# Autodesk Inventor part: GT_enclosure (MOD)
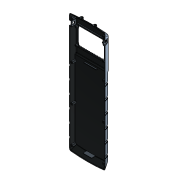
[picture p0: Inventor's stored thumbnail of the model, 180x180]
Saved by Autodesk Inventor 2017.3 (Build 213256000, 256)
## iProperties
Created: 2017-06
Part Number: GT_enclosure (MOD)
Material: ABS Plastic
Document SubType Name: Modeling
Designer: MQ42926084
Density: 1.06 g/cm^3
Appearance: Iron Gray
Mass: 305.571 g
Surface Area: 2134.12 cm^2
Volume: 288.274 cm^3
Author: MQ42926084
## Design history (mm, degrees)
sketch "Sketch1"
  geometry: L1 (-82, 271.181)-(-82, 0); L2 (82, 0)-(82, 271.181); L3 (0, -564)-(0, 416) reference; L4 (-120.006, 0)-(146.034, 0) reference; L5 (108.028, 276)-(-79.835, 276); L6 (82, 0)-(-82, 0); A1 r 700 centre (0, -424) between (82, 271.181) and (-82, 271.181); 1 further point
  constraints: 8 end point, 3 point on line, 2 point on circle, 1 centre point, 1 horizontal, 1 parallel, 1 tangent, 1 other
  dimensions: "d0" = 164 distance between parallel lines of L1 L2; "d4" = 700 radius of A1; "d8" = 276 distance between parallel lines of L4 L5
extrude "Extrusion1" new body sketch "Sketch1" distance "d2" = 25; taper "d3" = 0 deg
mirror "Mirror1"
workplane "Work Plane1"
sketch "Sketch7"
  geometry: L1 (0, -44.7)-(0, 268.2) reference; L2 (-80.78, 0)-(80.78, 0) reference; L3 (57.7, 223.5)-(-57.7, 223.5); L4 (-57.7, 223.5)-(-57.7, 142.5); L5 (-57.7, 142.5)-(57.7, 142.5); L6 (57.7, 142.5)-(57.7, 223.5); L7 (57.7, 183)-(-57.7, 183); 1 further point
  constraints: 10 end point, 2 midpoint, 2 parallel, 1 horizontal, 1 perpendicular, 1 other
  dimensions: "d67" = 81 distance between parallel lines of L5 L3; "d68" = 115.4 distance between parallel lines of L4 L6; "d69" = 183 distance between parallel lines of L7 L2
extrude "Extrusion7" cut sketch "Sketch7" distance "d70" = 108; taper "d71" = 0 deg
workplane "Work Plane2"
workplane "Work Plane4"
sketch "Sketch16"
  geometry: L1 (0, -386.4)-(0, 386.4) reference; L2 (-104.358, 0)-(104.076, 0) reference; L3 (72.3, -249)-(72.3, 251.8); C1 r 1.8 at (72.3, -249); C2 r 1.8 at (72.3, -85); C3 r 1.8 at (72.3, 79); C4 r 1.8 at (72.3, 251.8); 3 further points
  constraints: 4 centre point, 4 point on line, 2 end point, 1 coincident, 1 parallel
  dimensions: "d120" = 27 vertical distance of point (0, -276) L3.start; "d121" = 3.6 diameter of C1; "d125" = 144.6 diameter of L3 L1; "d129" = 3.6 diameter of C2 (derived); "d130" = 3.6 diameter of C3 (derived); "d131" = 3.6 diameter of C4 (derived); "d132" = 24.2 vertical distance of point (0, 276) L3.end; "d133" = 164 distance of C2.centre L3.start; "d134" = 164 distance of C3.centre C2.centre; "d135" = 172.8 distance of L3.end C3.centre (derived); "d311" = 249 distance from line of L2 L3.start
extrude "Extrusion13" cut sketch "Sketch16" distance "d126" = 16.8; taper "d127" = 0 deg
mirror "Mirror10"
chamfer "Chamfer6" distance "d141" = 25; stored, may be unused: second distance "d142" = 25, angle "d143" = 45 deg
chamfer "Chamfer7" distance "d144" = 23.7; stored, may be unused: second distance "d145" = 25, angle "d146" = 45 deg
chamfer "Chamfer8" distance "d147" = 25; stored, may be unused: second distance "d148" = 8, angle "d149" = 20 deg
chamfer "Chamfer9" distance "d150" = 25; stored, may be unused: second distance "d151" = 25, angle "d152" = 20 deg
sketch "Sketch17"
  geometry: L1 (-115, -106)-(115, -106); L2 (115, -106)-(115, 300); L3 (115, 300)-(-115, 300); L4 (-115, 300)-(-115, -106); L5 (0, 415.2)-(0, -391.2) reference; L6 (161, 0)-(-161, 0) reference; 1 further point
  constraints: 8 end point, 2 parallel, 1 horizontal, 1 perpendicular, 1 other
  dimensions: "d155" = 106 distance between parallel lines of L6 L1; "d156" = 230 distance between parallel lines of L2 L4; "d157" = 300 distance between parallel lines of L3 L6
extrude "Extrusion14" cut sketch "Sketch17" distance "d153" = 4; taper "d154" = 0 deg
fillet "Fillet19" dims "d158" = 10
fillet "Fillet20" dims "d159" = 4
fillet "Fillet21" dims "d160" = 6
fillet "Fillet22" dims "d161" = 6
workplane "Work Plane5"
workplane "Work Plane6"
sketch "Sketch21"
  geometry: L1 (18.7, 241.8)-(0, 241.8); L2 (0, 241.8)-(0, 221.8); L3 (0, 221.8)-(18.7, 221.8); L4 (18.7, 221.8)-(18.7, 241.8); L5 (0, 365.827)-(0, -365.797) reference; L6 (0, 261.63)-(0, -261.444) reference; L7 (-3.74, 0)-(22.44, 0) reference; L8 (0, 231.8)-(18.7, 231.8); 1 further point
  constraints: 10 end point, 2 midpoint, 2 parallel, 1 horizontal, 1 perpendicular, 1 point on line
  dimensions: "d182" = 20 distance between parallel lines of L3 L1; "d183" = 18.7 distance between parallel lines of L6 L4; "d314" = 231.8 distance between parallel lines of L8 L7
extrude "Extrusion17" cut sketch "Sketch21" distance "d180" = 29.5; taper "d181" = 0 deg
mirror "Mirror11"
workplane "Work Plane7"
shell "Shell11" dims "d204" = 3.1
sketch "Sketch22"
  geometry: L1 (0, 15.4)-(0, -15.4) reference; L2 (30.5, -5)-(30.5, 5); L3 (36.5, 0)-(36.5, 5); L4 (24.5, 5)-(24.5, 0); L5 (-80.78, 0)-(80.78, 0) reference; L6 (57.7, 0)-(-57.7, 0) reference; L7 (36.5, 0)-(24.5, 0); A1 r 6 centre (30.5, 5) between (36.5, 5) and (24.5, 5); 3 further points
  constraints: 10 end point, 4 point on line, 2 parallel, 2 point on circle, 2 tangent, 1 centre point, 1 midpoint, 1 vertical
  dimensions: "d190" = 30.5 distance between parallel lines of L1 L2; "d191" = 5 distance from line of L5 L2.end; "d192" = 12 distance between parallel lines of L4 L3
extrude "Extrusion18" join sketch "Sketch22" stored distance "d193" = 12; taper "d194" = 0 deg
mirror "Mirror12"
sketch "Sketch23"
  geometry: L1 (0, 12.845)-(0, -14.073) reference; L2 (-41.4, 0)-(6.9, 0) reference; L3 (-30.5, 5)-(-30.5, -6.227); L4 (-34.5, 5)-(-34.5, -6.227); L5 (-26.5, -6.227)-(-26.5, 5); A1 r 4 centre (-30.5, 5) between (-26.5, 5) and (-34.5, 5); A2 r 4 centre (-30.5, -6.227) between (-34.5, -6.227) and (-26.5, -6.227); 2 further points
  constraints: 8 end point, 4 point on circle, 4 tangent, 2 centre point, 2 parallel, 1 midpoint, 1 vertical
  dimensions: "d198" = 8 distance between parallel lines of L4 L5; "d199" = 30.5 distance between parallel lines of L1 L3; "d200" = 5 distance from line of L2 L3.start
extrude "Extrusion19" cut sketch "Sketch23" distance "d201" = 65; taper "d202" = 0 deg
mirror "Mirror13"
fillet "Fillet27" dims "d205" = 1
fillet "Fillet28" dims "d206" = 1.5
fillet "Fillet29" dims "d207" = 1.5
fillet "Fillet30" dims "d208" = 6
sketch "Sketch24"
  geometry: L1 (126.399, 113.5)-(10.999, 113.5) reference; L2 (126.399, 32.5)-(126.399, 113.5) reference; L3 (10.999, 32.5)-(126.399, 32.5) reference; L4 (10.999, 113.5)-(10.999, 32.5) reference; L5 (137.399, 119)-(-0.001, 119); L6 (-0.001, 119)-(-0.001, 27); L7 (-0.001, 27)-(137.399, 27); L8 (137.399, 27)-(137.399, 119); 1 further point
  constraints: 8 end point, 2 parallel, 1 horizontal, 1 perpendicular
  dimensions: "d209" = 5.5 distance between parallel lines of L7 L3; "d210" = 5.5 distance between parallel lines of L1 L5; "d211" = 11 distance between parallel lines of L2 L8; "d212" = 11 distance between parallel lines of L4 L6
extrude "Extrusion20" join sketch "Sketch24" distance "d213" = 4.5; taper "d214" = 0 deg
fillet "Fillet31" dims "d215" = 5
sketch "Sketch26"
  geometry: L1 (-28.4, 95)-(28.4, 95); L2 (28.4, 95)-(28.4, 93); L3 (28.4, 93)-(-28.4, 93); L4 (-28.4, 93)-(-28.4, 95); L5 (0, -19)-(0, 114) reference; L6 (-39.76, 0)-(39.76, 0) reference; 1 further point
  constraints: 8 end point, 2 parallel, 1 horizontal, 1 perpendicular, 1 other
  dimensions: "d217" = 2 distance between parallel lines of L1 L3; "d218" = 56.8 distance between parallel lines of L2 L4; "d219" = 93 distance between parallel lines of L6 L3
extrude "Extrusion21" join sketch "Sketch26" distance "d220" = 6; taper "d221" = 0 deg
sketch "Sketch27"
  geometry: L1 (-19.75, -254)-(19.75, -254); L2 (19.75, -254)-(19.75, -252); L3 (19.75, -252)-(-19.75, -252); L4 (-19.75, -252)-(-19.75, -254); L5 (0, -304.8)-(0, 50.8) reference; L6 (-27.65, 0)-(27.65, 0) reference; 1 further point
  constraints: 8 end point, 2 parallel, 1 horizontal, 1 perpendicular, 1 other
  dimensions: "d222" = 254 distance between parallel lines of L1 L6; "d223" = 2 distance between parallel lines of L1 L3; "d224" = 39.5 distance of L1.start L1.end
extrude "Extrusion22" join sketch "Sketch27" distance "d225" = 17.5; taper "d226" = 0 deg
sketch "Sketch28"
  geometry: L1 (0, 386.4)-(0, -386.4) reference; L2 (114.8, 0)-(-114.8, 0) reference; L3 (-68, -225.85)-(68, -225.85); L4 (68, -225.85)-(68, -140.15); L5 (68, -140.15)-(-68, -140.15); L6 (-68, -140.15)-(-68, -225.85); 1 further point
  constraints: 8 end point, 2 parallel, 1 horizontal, 1 perpendicular, 1 other
  dimensions: "d227" = 85.7 distance between parallel lines of L5 L3; "d228" = 136 distance between parallel lines of L4 L6; "d229" = 140.15 distance between parallel lines of L2 L5
extrude "Extrusion23" cut sketch "Sketch28" distance "d230" = 5; taper "d231" = 0 deg
sketch "Sketch29"
  geometry: L1 (0, 387.2)-(0, -391.2) reference; L2 (114.8, 0)-(-114.8, 0) reference; L3 (-6.45, -280)-(-0.85, -280); L4 (-0.85, -280)-(-0.85, -80); L5 (-0.85, -80)-(-6.45, -80); L6 (-6.45, -80)-(-6.45, -280); 1 further point
  constraints: 8 end point, 2 parallel, 1 horizontal, 1 perpendicular
  dimensions: "d232" = 5.6 distance between parallel lines of L4 L6; "d233" = 0.85 distance between parallel lines of L1 L4; "d234" = 80 distance between parallel lines of L5 L2; "d235" = 280 distance between parallel lines of L2 L3
extrude "Extrusion24" cut sketch "Sketch29" distance "d236" = 1.7; taper "d237" = 0 deg
pattern_linear "Rectangular Pattern6" dims "d240" = 7.3
mirror "Mirror14"
workplane "Work Plane8"
sketch "Sketch30"
  geometry: L1 (0, -13.9)-(0, 83.4) reference; L2 (-130.215, 0)-(21.703, 0) reference; L3 (-58.5, 65)-(-104.013, 65); L4 (-58.5, 69.5)-(-104.013, 69.5); L5 (-104.013, 60.5)-(-58.5, 60.5); A1 r 4.5 centre (-58.5, 65) between (-58.5, 60.5) and (-58.5, 69.5); A2 r 4.5 centre (-104.013, 65) between (-104.013, 69.5) and (-104.013, 60.5); 3 further points
  constraints: 8 end point, 5 point on circle, 4 tangent, 2 centre point, 1 horizontal, 1 midpoint, 1 parallel
  dimensions: "d242" = 9 distance between parallel lines of L5 L4; "d249" = 54 distance from line of L1 point (-54, 65); "d250" = 65 distance between parallel lines of L2 L3
extrude "Extrusion25" cut sketch "Sketch30" distance "d244" = 1.6; taper "d245" = 0 deg
pattern_linear "Rectangular Pattern7" dims "d248" = 57
mirror "Mirror15"
workplane "Work Plane9"
sketch "Sketch33"
  geometry: L1 (0, 30)-(0, -5) reference; L2 (-17.521, 0)-(105.126, 0) reference; L3 (79.605, 25)-(88.704, 0); L4 (88.704, 0)-(80.297, 0); L5 (74.5, 0)-(82, 0) reference; L6 (80.297, 0)-(71.198, 25); L7 (71.198, 25)-(79.605, 25); L8 (77.378, 12.7)-(82, 0) reference; 1 further point
  constraints: 8 end point, 3 parallel, 2 point on line
  dimensions: "d253" = 1.6 distance between parallel lines of L6 L8; "d254" = 25 distance between parallel lines of L2 L7
extrude "Extrusion26" cut sketch "Sketch33" stored distance "d255" = 9; taper "d256" = 0 deg
pattern_linear "Rectangular Pattern8" dims "d259" = 57
mirror "Mirror16"
fillet "Fillet32" dims "d260" = 6
fillet "Fillet33" dims "d261" = 0.8
mirror "Mirror17"
fillet "Fillet34" dims "d262" = 0.3
mirror "Mirror18"
sketch "Sketch34" dims "d265" = 91.5
  geometry: L1 (0, 416)-(0, -564) reference; L2 (114.8, 0)-(-114.8, 0) reference; L3 (26.95, 86)-(-27.05, 86); L4 (-27.05, 86)-(-27.05, 76); L5 (-27.05, 76)-(26.95, 76); L6 (26.95, 76)-(26.95, 86); L7 (26.95, 67)-(-13.05, 67); L8 (-13.05, 67)-(-13.05, 57); L9 (-13.05, 57)-(26.95, 57); L10 (26.95, 57)-(26.95, 67); L11 (26.95, 48)-(-27.05, 48); L12 (-27.05, 48)-(-27.05, 38); L13 (-27.05, 38)-(26.95, 38); L14 (26.95, 38)-(26.95, 48); L15 (0, 62)-(45.75, 62); C1 r 44.75 at (0, 62); C2 r 41.25 at (0, 62); C3 r 40.25 at (0, 62); A1 r 700 centre (0, -424) between (74.686, 272.004) and (-74.686, 272.004) reference; 5 further points
  constraints: 26 end point, 6 parallel, 4 horizontal, 4 point on line, 3 centre point, 3 coincident, 3 perpendicular, 2 midpoint, 1 horizontal alignment, 1 point on circle, 3 other
  dimensions: "d263" = 62 distance from line of L2 point (0, 62); "d266" = 89.5 diameter of C1; "d267" = 82.5 diameter of C2; "d268" = 80.5 diameter of C3; "d269" = 10 distance between parallel lines of L5 L3; "d270" = 10 distance between parallel lines of L9 L7 (derived); "d271" = 10 distance between parallel lines of L13 L11 (derived); "d272" = 9 distance between parallel lines of L7 L5; "d273" = 9 distance between parallel lines of L11 L9; "d274" = 26.95 distance between parallel lines of L1 L6; "d275" = 54 distance of L3.start L3.end; "d276" = 54 distance of L12.end L13.end (derived); "d277" = 40 distance between parallel lines of L8 L10; "d280" = 214 distance of C1.centre point (0, 276) (derived)
extrude "Extrusion27" cut sketch "Sketch34" distance "d278" = 1.5; taper "d279" = 0 deg
sketch "Sketch36"
  geometry: L1 (6.299, 36.5)-(6.299, 109.5); L2 (68.699, 277.753)-(68.699, -496.626) reference; L3 (-48.035, -110)-(185.431, -110) reference; C1 r 4 at (6.299, 36.5); C2 r 4 at (6.299, 109.5); 1 further point
  constraints: 2 centre point, 2 end point, 1 parallel
  dimensions: "d283" = 8 diameter of C1; "d284" = 8 diameter of C2 (derived); "d285" = 62.4 distance between parallel lines of L2 L1; "d286" = 73 distance of L1.start L1.end; "d287" = 146.5 distance from line of L3 L1.start
extrude "Extrusion28" join sketch "Sketch36" distance "d281" = 8.2; taper "d282" = 0 deg
mirror "Mirror19"
sketch "Sketch38"
  geometry: L1 (-59.5, 150.5)-(59.5, 150.5); L2 (59.5, 150.5)-(59.5, 215.5); L3 (59.5, 215.5)-(-59.5, 215.5); L4 (-59.5, 215.5)-(-59.5, 150.5); L5 (59.5, 183)-(-59.5, 183); L6 (0, -43.1)-(0, 258.6) reference; L7 (-83.3, 0)-(83.3, 0) reference; 1 further point
  constraints: 10 end point, 2 midpoint, 2 parallel, 1 horizontal, 1 perpendicular, 1 other
  dimensions: "d290" = 183 distance between parallel lines of L5 L7; "d291" = 65 distance between parallel lines of L3 L1; "d292" = 119 distance between parallel lines of L4 L2
extrude "Extrusion29" cut sketch "Sketch38" distance "d293" = 63; taper "d294" = 0 deg
fillet "Fillet35" dims "d295" = 10
fillet "Fillet36" dims "d296" = 10
fillet "Fillet37" dims "d297" = 1
sketch "Sketch39"
  geometry: C1 r 4 at (0, 0) reference; C2 r 4 at (0, 73) reference; 3 further points
  constraints: 2 coincident
hole "Hole1" sketch "Sketch39" at (0, 0), (0, 73) diameter "d298" = 3.242; stored, may be unused: countersink angle "d302" = 90 deg, drill point angle "d304" = 118 deg; dims "d299" = 8, "d300" = 4, "d301" = 2, "d303" = 11.8
mirror "Mirror20"
fillet "Fillet38" dims "d305" = 2
sketch "Sketch40"
  geometry: L1 (0, 285.24)-(0, -47.54) reference; L2 (-3, 0)-(18, 0) reference; L3 (14.6, 233.935)-(14.6, 229.665); L4 (3.6, 233.935)-(3.6, 229.665); L5 (9.1, 237.7)-(9.1, 225.9); A1 r 5.9 centre (9.1, 231.8) between (14.6, 233.935) and (3.6, 233.935); A2 r 5.9 centre (9.1, 231.8) between (3.6, 229.665) and (14.6, 229.665); 2 further points
  constraints: 6 end point, 6 point on circle, 3 vertical, 2 centre point, 1 coincident, 1 midpoint, 1 other
  dimensions: "d306" = 231.8 distance from line of L2 A1.centre; "d307" = 9.1 distance from line of L1 A1.centre; "d322" = 5.9 radius of A2; "d323" = 11 distance between parallel lines of L3 L4
extrude "Extrusion30" cut sketch "Sketch40" stored distance "d309" = 63; taper "d310" = 0 deg
mirror "Mirror21"
sketch "Sketch41"
  geometry: C1 r 4.9 at (72.3, -249) reference; C2 r 4.9 at (72.3, -85) reference; C3 r 4.9 at (72.3, 79) reference; C4 r 4.9 at (72.3, 251.8) reference; C5 r 4.9 at (-72.3, 251.8) reference; C6 r 4.9 at (-72.3, 79) reference; C7 r 4.9 at (-72.3, -85) reference; C8 r 4.9 at (-72.3, -249) reference; 1 further point
  dimensions: "d316" = 9.8 diameter of C4 (derived)
extrude "Extrusion31" cut sketch "Sketch41" distance "d312" = 1; taper "d313" = 0 deg
body "Solid1"
other parameters: "d66" = 25, "d118" = 0, "d169" = 12.7, "d179" = 74.5, "d189" = 276.5, "d241" = 21, "d252" = 65, "d308" = 11.8
